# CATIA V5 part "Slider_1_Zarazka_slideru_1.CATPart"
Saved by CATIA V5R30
Part number: Slider_1_Zarazka_slideru_1
Publications: "DrillHole_CapScrew_E1200_1.2_"
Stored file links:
  E:\Bakalarka\Model\Forma_v7\Slider_1_Zarazka_slideru_1.CATPart
  E:\Bakalarka\Model\Forma_v7\Forma.CATProduct
  E:\Bakalarka\Model\Forma_v7\TlgItf_Zarazka_slideru.CATProduct

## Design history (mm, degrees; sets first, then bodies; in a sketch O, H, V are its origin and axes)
Body1 (main body)
Body2 "DrillHole"
  Solid1: linked copy from another document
